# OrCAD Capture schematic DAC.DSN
size A
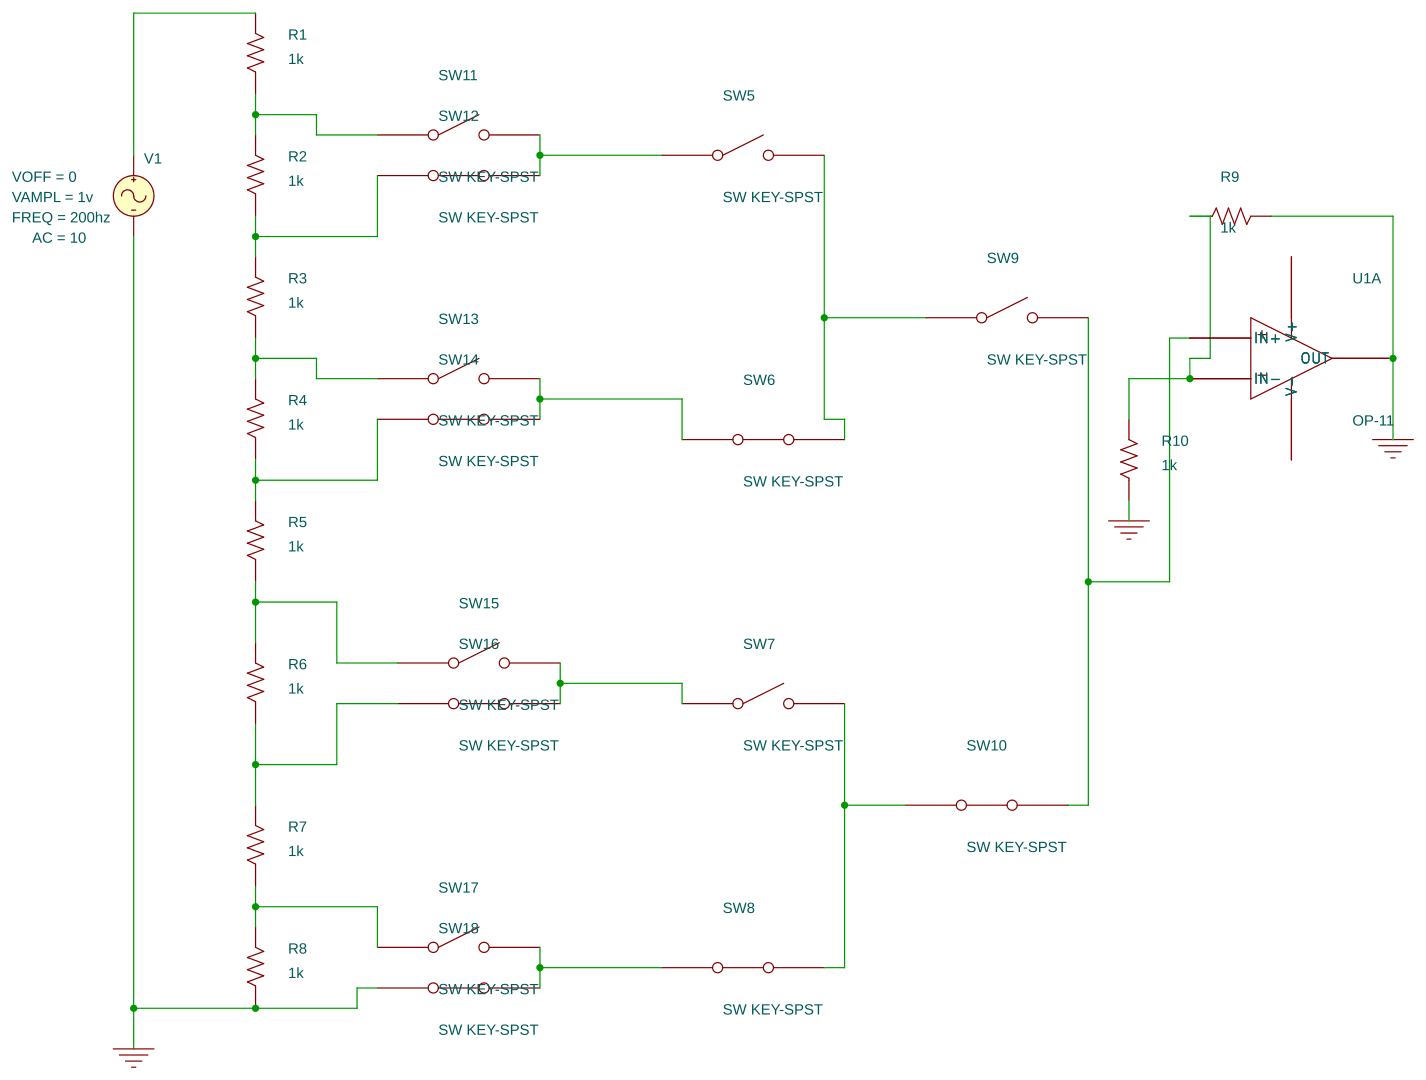
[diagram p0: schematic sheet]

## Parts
R1  1k  [AX/RC05]
R2  1k  [AX/RC05]
R3  1k  [AX/RC05]
R4  1k  [AX/RC05]
R5  1k  [AX/RC05]
R6  1k  [AX/RC05]
R7  1k  [AX/RC05]
R8  1k  [AX/RC05]
R9  1k  [AX/RC05]
R10  1k  [AX/RC05]
SW5  SW KEY-SPST
SW6  SW KEY-SPST
SW7  SW KEY-SPST
SW8  SW KEY-SPST
SW9  SW KEY-SPST
SW10  SW KEY-SPST
SW11  SW KEY-SPST
SW12  SW KEY-SPST
SW13  SW KEY-SPST
SW14  SW KEY-SPST
SW15  SW KEY-SPST
SW16  SW KEY-SPST
SW17  SW KEY-SPST
SW18  SW KEY-SPST
U1  OP-11  (section A)
V1  VSIN

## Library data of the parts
R1-R10 = r
SW5 SW7 SW9 SW11 SW13 SW15 SW17 = SW_KEY-SPST
SW6 = SW_KEY-SPST_4
SW8 = SW_KEY-SPST_5
SW10 = SW_KEY-SPST_6
SW12 = SW_KEY-SPST_0
SW14 = SW_KEY-SPST_1
SW16 = SW_KEY-SPST_2
SW18 = SW_KEY-SPST_3
U1 = OP-11
V1 = VSIN: AC: 10; FREQ: 200hz; VAMPL: 1v; VOFF: 0

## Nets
0: R8.1 R9.2 R10.1 SW18.1 U1.1(OUT) V1.2(-)
V+: U1.4(V+)
V-: U1.11(V-)
N00197: R1.2 V1.1(+)
N00204: R1.1 R2.2 SW11.1
N00208: R2.1 R3.2 SW12.1
N00212: R3.1 R4.2 SW13.1
N00216: R4.1 R5.2 SW14.1
N00220: R5.1 R6.2 SW15.1
N00224: R6.1 R7.2 SW16.1
N00228: R7.1 R8.2 SW17.1
N00697: SW7.1 SW15.2 SW16.2
N00701: SW6.1 SW13.2 SW14.2
N00705: SW8.1 SW17.2 SW18.2
N00745: SW5.1 SW11.2 SW12.2
N00759: SW5.2 SW6.2 SW9.1
N00783: SW7.2 SW8.2 SW10.1
N00803: SW9.2 SW10.2 U1.3(IN+)
N00847: R9.1 R10.2 U1.2(IN-)
